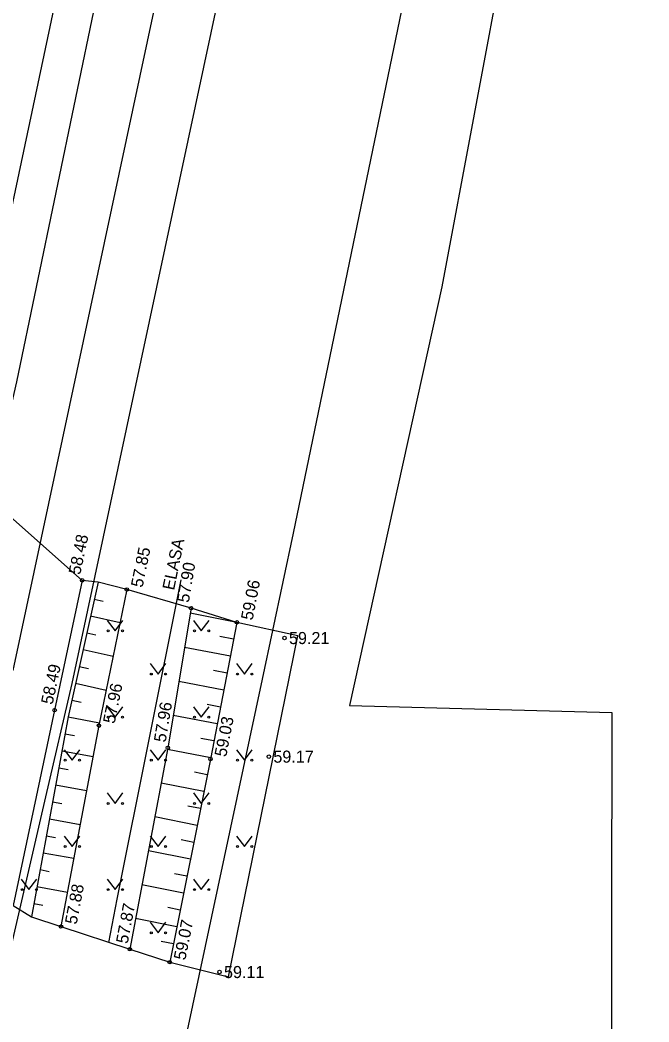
# Model space of a CAD drawing. Extents: x 580119 to 583377, y 6518915 to 6520820.
# Drawn here: x 582130.5 to 582167, y 6520042.3 to 6520100.4 of the extents above; entities that cross this region are included whole.
import ezdxf

# ---------------------------------------------------------------- set-up
doc = ezdxf.new("R2010")
doc.units = 0
for name, color, linetype in [('HALJASTUS', 7, 'Continuous'), ('KORGUS-EH2000', 7, 'Continuous'), ('MOOTPIIR', 7, 'Continuous'), ('MPOHULIIN', 7, 'Continuous'), ('PIIR', 7, 'Continuous'), ('RELJEEF', 7, 'Continuous'), ('SITRASS', 7, 'Continuous'), ('TEE', 7, 'Continuous'), ('Tee Liiklusala', 7, 'Continuous'), ('Tee Rada Pinnas', 7, 'Continuous'), ('Tee Tänav Püsikate', 7, 'Continuous')]:
    doc.layers.add(name, color=color, linetype=linetype)

msp = doc.modelspace()

# ---------------------------------------------------------------- linework, layer by layer
at = {"layer": 'HALJASTUS'}
for p, q in [((582135.537, 6520065.607), (582136, 6520065)), ((582136, 6520065), (582136.446, 6520065.607)), ((582140.537, 6520065.607), (582141, 6520065)), ((582141, 6520065), (582141.446, 6520065.607)), ((582138.037, 6520063.107), (582138.5, 6520062.5)), ((582138.5, 6520062.5), (582138.946, 6520063.107)), ((582143.037, 6520063.107), (582143.5, 6520062.5)), ((582143.5, 6520062.5), (582143.946, 6520063.107)), ((582135.537, 6520060.607), (582136, 6520060)), ((582136, 6520060), (582136.446, 6520060.607)), ((582140.537, 6520060.607), (582141, 6520060)), ((582141, 6520060), (582141.446, 6520060.607)), ((582133.037, 6520058.107), (582133.5, 6520057.5)), ((582133.5, 6520057.5), (582133.946, 6520058.107)), ((582138.037, 6520058.107), (582138.5, 6520057.5)), ((582138.5, 6520057.5), (582138.946, 6520058.107)), ((582143.037, 6520058.107), (582143.5, 6520057.5)), ((582143.5, 6520057.5), (582143.946, 6520058.107)), ((582135.537, 6520055.607), (582136, 6520055)), ((582136, 6520055), (582136.446, 6520055.607)), ((582140.537, 6520055.607), (582141, 6520055)), ((582141, 6520055), (582141.446, 6520055.607)), ((582133.037, 6520053.107), (582133.5, 6520052.5)), ((582133.5, 6520052.5), (582133.946, 6520053.107)), ((582138.037, 6520053.107), (582138.5, 6520052.5)), ((582138.5, 6520052.5), (582138.946, 6520053.107)), ((582143.037, 6520053.107), (582143.5, 6520052.5)), ((582143.5, 6520052.5), (582143.946, 6520053.107)), ((582130.537, 6520050.607), (582131, 6520050)), ((582131, 6520050), (582131.446, 6520050.607)), ((582135.537, 6520050.607), (582136, 6520050)), ((582136, 6520050), (582136.446, 6520050.607)), ((582140.537, 6520050.607), (582141, 6520050)), ((582141, 6520050), (582141.446, 6520050.607)), ((582138.037, 6520048.107), (582138.5, 6520047.5)), ((582138.5, 6520047.5), (582138.946, 6520048.107))]:
    msp.add_line(p, q, dxfattribs=at)
for centre in [(582135.599, 6520065), (582136.428, 6520065), (582140.599, 6520065), (582141.428, 6520065), (582138.099, 6520062.5), (582138.928, 6520062.5), (582143.099, 6520062.5), (582143.928, 6520062.5), (582135.599, 6520060), (582136.428, 6520060), (582140.599, 6520060), (582141.428, 6520060), (582133.099, 6520057.5), (582133.928, 6520057.5), (582138.099, 6520057.5), (582138.928, 6520057.5), (582143.099, 6520057.5), (582143.928, 6520057.5), (582135.599, 6520055), (582136.428, 6520055), (582140.599, 6520055), (582141.428, 6520055), (582133.099, 6520052.5), (582133.928, 6520052.5), (582138.099, 6520052.5), (582138.928, 6520052.5), (582143.099, 6520052.5), (582143.928, 6520052.5), (582130.599, 6520050), (582131.428, 6520050), (582135.599, 6520050), (582136.428, 6520050), (582140.599, 6520050), (582141.428, 6520050), (582138.099, 6520047.5), (582138.928, 6520047.5)]:
    msp.add_circle(centre, 0.055, dxfattribs=at)
at = {"layer": 'KORGUS-EH2000'}
for centre in [(582134.086, 6520067.931), (582136.677, 6520067.402), (582140.403, 6520066.321), (582143.065, 6520065.496), (582145.826, 6520064.588), (582132.487, 6520060.406), (582135.057, 6520059.508), (582139.056, 6520058.222), (582144.919, 6520057.71), (582141.532, 6520057.574), (582132.856, 6520047.858), (582136.85, 6520046.543), (582139.163, 6520045.794), (582142.056, 6520045.223)]:
    msp.add_circle(centre, 0.1, dxfattribs=at)
at = {"layer": 'MOOTPIIR'}
msp.add_lwpolyline([(582130.076, 6520049.073), (582131.143, 6520048.427), (582132.856, 6520047.858), (582136.85, 6520046.543), (582139.163, 6520045.794), (582142.577, 6520044.943), (582146.594, 6520064.716), (582143.065, 6520065.496), (582140.403, 6520066.321), (582136.677, 6520067.402), (582135.007, 6520067.82), (582134.086, 6520067.931), (582129.037, 6520072.39)], dxfattribs=at)
at = {"layer": 'MPOHULIIN'}
msp.add_lwpolyline([(582126.022, 6520070.815), (582135.926, 6520117.476)], dxfattribs=at)
at = {"layer": 'PIIR'}
msp.add_lwpolyline([(582158.7, 6520104.98), (582154.96, 6520084.94), (582149.6, 6520060.67), (582164.81, 6520060.27), (582164.78, 6520035.55), (582160.42, 6520035.61), (582143.96, 6519961.25), (582094.14, 6519961.8), (582065.39, 6519977.21), (582105.65, 6520019.17), (582114.76, 6520028.68), (582120.68, 6520059.28), (582123.3, 6520072.1), (582132.28, 6520117.79)], dxfattribs=at)
at = {"layer": 'RELJEEF'}
for p, q in [((582134.789, 6520066.844), (582135.298, 6520066.73)), ((582143.065, 6520065.496), (582140.353, 6520066.021)), ((582134.572, 6520065.868), (582136.284, 6520065.486)), ((582134.354, 6520064.892), (582134.873, 6520064.776)), ((582142.875, 6520064.514), (582142.069, 6520064.67)), ((582134.137, 6520063.916), (582135.882, 6520063.527)), ((582142.685, 6520063.532), (582140.025, 6520064.047)), ((582133.919, 6520062.939), (582134.448, 6520062.822)), ((582142.495, 6520062.55), (582141.705, 6520062.703)), ((582133.702, 6520061.963), (582135.479, 6520061.567)), ((582142.305, 6520061.569), (582139.697, 6520062.073)), ((582133.484, 6520060.987), (582134.022, 6520060.867)), ((582142.115, 6520060.587), (582141.34, 6520060.737)), ((582133.267, 6520060.011), (582135.091, 6520059.677)), ((582141.925, 6520059.605), (582139.368, 6520060.1)), ((582133.087, 6520059.028), (582133.632, 6520058.928)), ((582141.735, 6520058.623), (582140.976, 6520058.77)), ((582132.906, 6520058.044), (582134.717, 6520057.712)), ((582141.545, 6520057.641), (582139.038, 6520058.127)), ((582132.726, 6520057.06), (582133.268, 6520056.961)), ((582141.348, 6520056.661), (582140.6, 6520056.811)), ((582132.545, 6520056.077), (582134.346, 6520055.747)), ((582141.151, 6520055.681), (582138.67, 6520056.179)), ((582132.365, 6520055.093), (582132.904, 6520054.994)), ((582140.954, 6520054.7), (582140.213, 6520054.849)), ((582132.185, 6520054.11), (582133.975, 6520053.781)), ((582140.757, 6520053.72), (582138.299, 6520054.214)), ((582132.004, 6520053.126), (582132.54, 6520053.028)), ((582140.56, 6520052.739), (582139.826, 6520052.887)), ((582131.824, 6520052.142), (582133.603, 6520051.816)), ((582140.363, 6520051.759), (582137.928, 6520052.249)), ((582131.644, 6520051.159), (582132.176, 6520051.061)), ((582140.165, 6520050.779), (582139.438, 6520050.925)), ((582139.968, 6520049.798), (582137.557, 6520050.283)), ((582131.463, 6520050.175), (582133.232, 6520049.851)), ((582131.283, 6520049.192), (582131.812, 6520049.095)), ((582139.771, 6520048.818), (582139.051, 6520048.963)), ((582139.574, 6520047.838), (582137.185, 6520048.318)), ((582139.377, 6520046.857), (582138.664, 6520047.001))]:
    msp.add_line(p, q, dxfattribs=at)
for points in [[(582135.007, 6520067.82), (582133.267, 6520060.014), (582131.143, 6520048.427)], [(582136.677, 6520067.402), (582135.057, 6520059.508), (582132.856, 6520047.858)], [(582140.403, 6520066.321), (582139.056, 6520058.222), (582136.85, 6520046.543)], [(582143.065, 6520065.496), (582141.532, 6520057.574), (582139.163, 6520045.794)]]:
    msp.add_lwpolyline(points, dxfattribs=at)
at = {"layer": 'SITRASS'}
msp.add_lwpolyline([(582135.634, 6520046.943), (582136.122, 6520049.445), (582139.831, 6520067.961)], dxfattribs=at)
at = {"layer": 'TEE'}
msp.add_lwpolyline([(582134.086, 6520067.931), (582132.487, 6520060.406), (582130.076, 6520049.073)], dxfattribs=at)
at = {"layer": 'Tee Liiklusala'}
for points in [[(581995.761, 6520145.993), (582073.573, 6520099.108), (582121.605, 6520070.199), (582125.334, 6520070.484), (582127.654, 6520071.327), (582128.937, 6520073.607), (582130.287, 6520079.432), (582138.275, 6520117.888)], [(582145.121, 6520116.426), (582133.485, 6520061.957), (582131.961, 6520055.386), (582129.979, 6520046.844), (582126.039, 6520031.735), (582123.002, 6520021.635), (582120.961, 6520016.267), (582118.863, 6520012.212), (582116.854, 6520008.97), (582111.576, 6520000), (582089.135, 6519971.687), (582088.01, 6519968.68), (582087.97, 6519964.75), (582089.51, 6519961.97), (582093.04, 6519960.36), (582098.21, 6519959.668), (582113.375, 6519959.835), (582120.318, 6519959.719), (582129.62, 6519959.56)]]:
    msp.add_lwpolyline(points, dxfattribs=at)
at = {"layer": 'Tee Rada Pinnas'}
msp.add_lwpolyline([(582120.704, 6519960.669), (582123.04, 6519966.421), (582130.88, 6520000), (582131.578, 6520002.989), (582133.369, 6520010.661), (582135.3, 6520018.94), (582144.541, 6520062.2), (582146.35, 6520070.661), (582174.6, 6520206.991), (582185.24, 6520261.097), (582187.1, 6520266.009), (582189.33, 6520270.502)], dxfattribs=at)
at = {"layer": 'Tee Tänav Püsikate'}
msp.add_lwpolyline([(582152.59, 6520168.142), (582130.065, 6520062.702)], dxfattribs=at)

# ---------------------------------------------------------------- texts
at = {"layer": 'KORGUS-EH2000'}
for s, rotation, p in [(' 58.48', 78.00122, (582133.915, 6520067.968)), (' 57.85', 78.40129, (582137.534, 6520067.226)), (' 57.90', 80.55385, (582140.231, 6520066.35)), (' 59.06', 79.04364, (582143.924, 6520065.329)), (' 58.49', 78.00122, (582132.316, 6520060.443)), (' 57.96', 78.40129, (582135.914, 6520059.332)), (' 57.96', 80.55385, (582138.883, 6520058.251)), (' 59.03', 79.04364, (582142.391, 6520057.407)), (' 57.88', 79.3009, (582133.715, 6520047.696)), (' 57.87', 79.30498, (582136.678, 6520046.575)), (' 59.07', 78.63087, (582140.021, 6520045.622))]:
    msp.add_text(s, height=0.7, rotation=rotation, dxfattribs=at).set_placement(p)
for s, p in [(' 59.21', (582145.826, 6520064.237)), (' 59.17', (582144.919, 6520057.36)), (' 59.11', (582142.056, 6520044.873))]:
    msp.add_text(s, height=0.7, dxfattribs=at).set_placement(p)
at = {"layer": 'SITRASS'}
msp.add_text('ELASA', height=0.7, rotation=78.40998, dxfattribs=at).set_placement((582139.416, 6520067.323))

doc.saveas('drawing.dxf')
